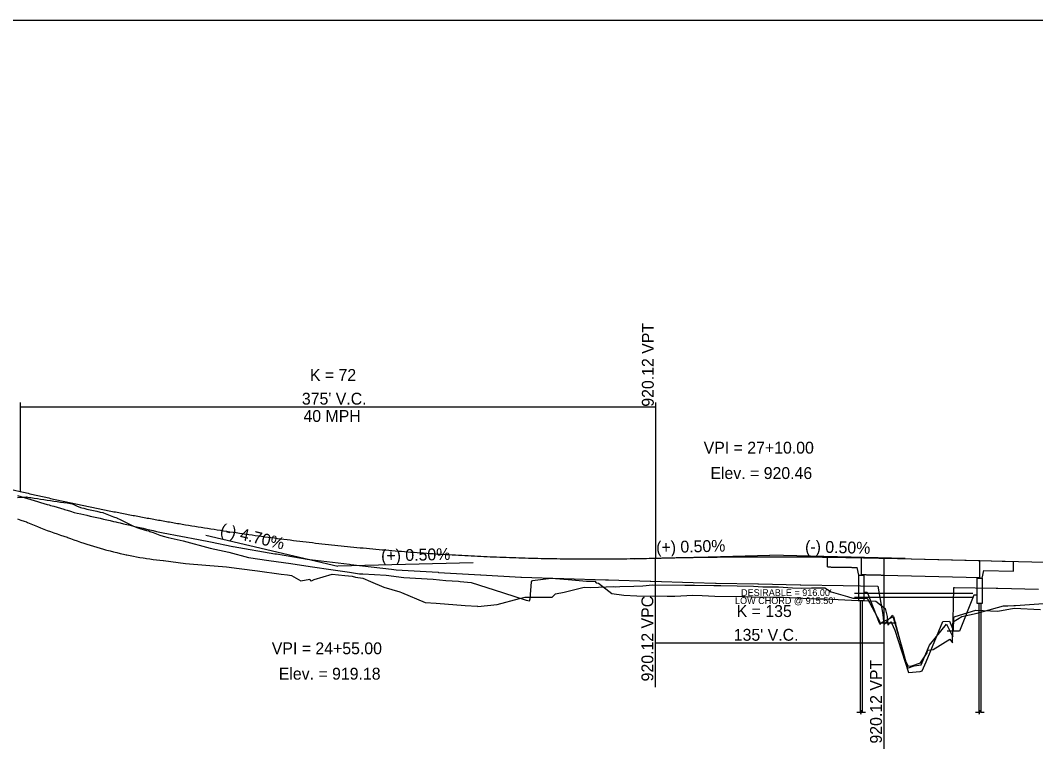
# Model space of a CAD drawing. Extents: x 1538426 to 1542651, y 1162537 to 1163637.
# Drawn here: x 1539693 to 1540293, y 1163207 to 1163637 of the extents above; entities that cross this region are included whole.
import ezdxf

# ---------------------------------------------------------------- set-up
doc = ezdxf.new("R2010")
doc.units = 0
for name, color, linetype in [('BR_CONCRETE', 7, 'Continuous'), ('BR_EXIST_GROUND_LT', 7, 'Continuous'), ('BR_EXIST_GROUND_RT', 7, 'Continuous'), ('BR_GROUND LINES', 7, 'Continuous'), ('BR_USER NOTES', 7, 'Continuous'), ('RD_DDB_GradeTX', 7, 'Continuous'), ('RD_DDB_Profile_EX', 7, 'Continuous'), ('RD_DDB_Profile_Lbl', 7, 'Continuous'), ('RD_DDB_Profile_PR', 7, 'Continuous'), ('RD_DDB_StripGrade', 7, 'Continuous'), ('RD_DDB_VCLbl', 7, 'Continuous'), ('RD_SHT_ShtClip', 7, 'Continuous')]:
    doc.layers.add(name, color=color, linetype=linetype)

msp = doc.modelspace()

# ---------------------------------------------------------------- linework, layer by layer
at = {"layer": 'BR_CONCRETE'}
for p, q in [((1540169.92, 1163314.12), (1540169.92, 1163319.95)), ((1540189.92, 1163319.63), (1540189.92, 1163309.63)), ((1540203.42, 1163319.33), (1540259.92, 1163317.92)), ((1540188.42, 1163309.21), (1540187.5, 1163313.84)), ((1540259.92, 1163307.92), (1540259.92, 1163317.92)), ((1540259.92, 1163317.92), (1540279.92, 1163317.42)), ((1540279.92, 1163311.59), (1540279.92, 1163317.42)), ((1540189.92, 1163309.63), (1540189.92, 1163309.21)), ((1540203.41, 1163309.33), (1540259.92, 1163307.92)), ((1540259.92, 1163307.92), (1540259.92, 1163307.5)), ((1540261.42, 1163307.5), (1540262.33, 1163312.03)), ((1540262.33, 1163312.03), (1540279.92, 1163311.59)), ((1540189.34, 1163294.21), (1540189.34, 1163228.4)), ((1540190.51, 1163294.21), (1540190.51, 1163228.4)), ((1540259.34, 1163292.5), (1540259.34, 1163228.4)), ((1540260.51, 1163292.5), (1540260.51, 1163228.4))]:
    msp.add_line(p, q, dxfattribs=at)
for points in [[(1540188.42, 1163309.21), (1540191.42, 1163309.21), (1540191.42, 1163294.21), (1540188.42, 1163294.21)], [(1540258.42, 1163307.5), (1540261.42, 1163307.5), (1540261.42, 1163292.5), (1540258.42, 1163292.5)]]:
    msp.add_lwpolyline(points, close=True, dxfattribs=at)
for points in [[(1540187.32, 1163228.4), (1540189.56, 1163228.4), (1540189.65, 1163227.23), (1540190.16, 1163229.64), (1540190.34, 1163228.4), (1540192.45, 1163228.4)], [(1540257.32, 1163228.4), (1540259.56, 1163228.4), (1540259.65, 1163227.23), (1540260.16, 1163229.64), (1540260.34, 1163228.4), (1540262.45, 1163228.4)]]:
    msp.add_lwpolyline(points, dxfattribs=at)
for points in [[(1540169.92, 1163319.95), (1540176.59, 1163319.87), (1540183.26, 1163319.76), (1540189.92, 1163319.63)], [(1540189.92, 1163319.63), (1540194.42, 1163319.54), (1540198.92, 1163319.44), (1540203.42, 1163319.33)], [(1540169.92, 1163314.12), (1540175.78, 1163314.05), (1540181.64, 1163313.95), (1540187.5, 1163313.84)], [(1540189.92, 1163309.63), (1540194.42, 1163309.54), (1540198.92, 1163309.44), (1540203.41, 1163309.33)]]:
    msp.add_open_spline(points, degree=2, dxfattribs=at)
at = {"layer": 'BR_EXIST_GROUND_LT'}
msp.add_lwpolyline([(1539691.76, 1163342.52), (1539693.72, 1163341.83), (1539695.67, 1163341.16), (1539697, 1163340.71), (1539697.63, 1163340.44), (1539699.58, 1163339.61), (1539701.53, 1163338.8), (1539703.49, 1163338), (1539705.44, 1163337.22), (1539707.4, 1163336.46), (1539709.35, 1163335.72), (1539711.31, 1163334.99), (1539712.2, 1163334.67), (1539713.26, 1163334.28), (1539715.21, 1163333.59), (1539717.17, 1163332.92), (1539719.12, 1163332.26), (1539721.08, 1163331.62), (1539721.38, 1163331.53), (1539723.03, 1163330.91), (1539724.98, 1163330.2), (1539726.94, 1163329.5), (1539728.89, 1163328.83), (1539730.85, 1163328.17), (1539731.59, 1163327.92), (1539732.8, 1163327.53), (1539734.76, 1163326.91), (1539736.71, 1163326.31), (1539738.66, 1163325.73), (1539740.62, 1163325.17), (1539742.57, 1163324.62), (1539743.72, 1163324.31), (1539744.53, 1163324.09), (1539746.48, 1163323.58), (1539748.43, 1163323.08), (1539750.39, 1163322.61), (1539752.34, 1163322.15), (1539754.3, 1163321.71), (1539755.85, 1163321.37), (1539756.25, 1163321.29), (1539758.21, 1163320.89), (1539760.16, 1163320.51), (1539762.11, 1163320.15), (1539764.07, 1163319.8), (1539766.02, 1163319.48), (1539767.2, 1163319.29), (1539767.98, 1163319.17), (1539769.93, 1163318.87), (1539771.88, 1163318.6), (1539773.84, 1163318.34), (1539775.79, 1163318.1), (1539777.75, 1163317.88), (1539778.05, 1163317.85), (1539791.04, 1163316.23), (1539803.05, 1163315.2), (1539815.1, 1163314.17), (1539822.57, 1163313.25), (1539833.4, 1163311.84), (1539847.53, 1163309.93), (1539851.16, 1163309.44), (1539853.56, 1163309.13), (1539859.05, 1163306.01), (1539864.41, 1163306.87), (1539864.6, 1163306.17), (1539865.38, 1163305.92), (1539867, 1163306.65), (1539877.6, 1163309.83), (1539884.94, 1163309.05), (1539889.36, 1163308.65), (1539891.28, 1163308.15), (1539895.66, 1163307.59), (1539900.16, 1163305.57), (1539908.15, 1163302.15), (1539917.52, 1163299.43), (1539918.52, 1163298.96), (1539932.53, 1163293.22), (1539938.94, 1163292.75), (1539956.06, 1163291.43), (1539963.28, 1163290.91), (1539963.62, 1163290.88), (1539974.97, 1163291.9), (1539988.11, 1163295.5), (1539991.25, 1163296.36), (1540007.49, 1163296.2), (1540009.46, 1163298.24), (1540014.57, 1163299.25), (1540026.4, 1163302.23), (1540030.3, 1163302.08), (1540043.79, 1163302.53), (1540045.04, 1163302.47), (1540047.34, 1163302.66), (1540055.58, 1163302.77), (1540061.06, 1163303.08), (1540066.72, 1163303.67), (1540085.71, 1163303.3), (1540091.4, 1163303.47), (1540102.86, 1163303.24), (1540107.11, 1163303.1), (1540126.41, 1163302.87), (1540131.8, 1163302.47), (1540135.2, 1163302.33), (1540141.03, 1163302.34), (1540149.41, 1163301.79), (1540154.44, 1163301.64), (1540160.51, 1163301.89), (1540168.35, 1163301.8), (1540172.12, 1163299.53), (1540181.86, 1163296.62), (1540184.97, 1163295.74), (1540193.52, 1163295.73), (1540200.73, 1163282.11), (1540200.94, 1163280.18), (1540202.22, 1163281.63), (1540209.05, 1163284.8), (1540215.91, 1163259.21), (1540217.48, 1163255.85), (1540219.15, 1163255.51), (1540224.95, 1163257.53), (1540228.87, 1163263.48), (1540229.1, 1163264.78), (1540229.54, 1163264.93), (1540232.39, 1163265.34), (1540242.17, 1163271.48), (1540243.74, 1163269.26), (1540243.97, 1163280.57), (1540244.12, 1163281.73), (1540249.37, 1163284.98), (1540258.46, 1163286.84), (1540273.95, 1163291.17), (1540276.4, 1163291.26), (1540279.95, 1163291.29), (1540280.94, 1163291.31), (1540297.45, 1163292.46)], dxfattribs=at)
at = {"layer": 'BR_EXIST_GROUND_RT'}
msp.add_lwpolyline([(1539691.76, 1163355.18), (1539693.72, 1163355.29), (1539695.67, 1163355.4), (1539697.16, 1163355.42), (1539697.63, 1163355.34), (1539698.91, 1163355.18), (1539699.58, 1163355.07), (1539701.53, 1163354.76), (1539703.49, 1163354.45), (1539705.44, 1163354.14), (1539707.4, 1163353.85), (1539709.35, 1163353.55), (1539711.31, 1163353.27), (1539713.26, 1163352.98), (1539715.21, 1163352.71), (1539717.17, 1163352.43), (1539719.12, 1163352.17), (1539721.08, 1163351.9), (1539723.03, 1163351.65), (1539723.66, 1163351.57), (1539724.98, 1163350.94), (1539726.94, 1163350.03), (1539728.48, 1163349.31), (1539728.89, 1163349.21), (1539729.83, 1163348.99), (1539730.85, 1163348.75), (1539732.8, 1163348.29), (1539734.76, 1163347.84), (1539736.71, 1163347.39), (1539738.66, 1163346.95), (1539740.62, 1163346.52), (1539742.1, 1163346.19), (1539742.57, 1163345.98), (1539744.53, 1163345.24), (1539746.48, 1163344.5), (1539748.43, 1163343.76), (1539750.39, 1163343.03), (1539750.7, 1163342.92), (1539752.34, 1163342.08), (1539754.3, 1163341.11), (1539756.25, 1163340.15), (1539758.21, 1163339.22), (1539760.16, 1163338.29), (1539762.26, 1163337.32), (1539764.07, 1163336.81), (1539766.02, 1163336.26), (1539767.98, 1163335.73), (1539769.34, 1163335.36), (1539769.93, 1163335.14), (1539771.88, 1163334.41), (1539773.84, 1163333.69), (1539775.79, 1163332.98), (1539777.75, 1163332.31), (1539780.67, 1163331.56), (1539789.63, 1163329.52), (1539805.59, 1163325.24), (1539816.46, 1163322.8), (1539828.12, 1163319.74), (1539840.22, 1163317.91), (1539853.12, 1163316.07), (1539864.6, 1163314.34), (1539878.11, 1163312.42), (1539887.83, 1163311.04), (1539893.65, 1163310.16), (1539895.65, 1163309.97), (1539909.43, 1163309.26), (1539919.9, 1163307.88), (1539937.15, 1163306.92), (1539944.57, 1163306.1), (1539952.17, 1163305.66), (1539953.17, 1163305.56), (1539959.65, 1163304.86), (1539978.18, 1163298.97), (1539978.66, 1163298.93), (1539992.06, 1163294.56), (1539994.15, 1163294.19), (1539994.39, 1163295.35), (1539995.26, 1163305.41), (1539995.77, 1163306.09), (1540006.78, 1163307.59), (1540016.83, 1163306.72), (1540027.73, 1163305.83), (1540032.32, 1163305.76), (1540032.64, 1163305.75), (1540033.49, 1163304.73), (1540034.72, 1163304.48), (1540042.72, 1163298.45), (1540049.85, 1163297.42), (1540057.5, 1163297.13), (1540075.39, 1163296.98), (1540079.96, 1163296.83), (1540090.6, 1163297.39), (1540096.03, 1163297.31), (1540103.44, 1163296.87), (1540121.14, 1163296.69), (1540125.63, 1163296.46), (1540138.16, 1163296.35), (1540144.05, 1163296.28), (1540163.17, 1163295.35), (1540168.48, 1163295.29), (1540188.19, 1163294.31), (1540190.29, 1163294.28), (1540198.55, 1163293.87), (1540203.36, 1163290.21), (1540204.13, 1163289.6), (1540205.2, 1163284.96), (1540205.66, 1163279.77), (1540207.48, 1163281.65), (1540207.84, 1163281.06), (1540209.79, 1163276.83), (1540217.79, 1163251.79), (1540224.64, 1163252.49), (1540225.87, 1163252.74), (1540228.23, 1163258.07), (1540238.16, 1163281.98), (1540242.05, 1163282.1), (1540244.43, 1163276.45), (1540244.53, 1163284.44), (1540245.32, 1163284.97), (1540257.53, 1163288.63), (1540270.61, 1163288.09), (1540280.3, 1163289.71), (1540295.74, 1163289.08)], dxfattribs=at)
at = {"layer": 'BR_GROUND LINES'}
for p, q in [((1540191.42, 1163299.21), (1540193.42, 1163299.21)), ((1540193.42, 1163299.21), (1540200.61, 1163281.24)), ((1540256.42, 1163297.5), (1540247.92, 1163276.24)), ((1540258.42, 1163297.5), (1540256.42, 1163297.5)), ((1540200.61, 1163281.24), (1540210.52, 1163281.24)), ((1540247.92, 1163276.24), (1540240.6, 1163276.24))]:
    msp.add_line(p, q, dxfattribs=at)
at = {"layer": 'BR_USER NOTES'}
for p, q in [((1540185.92, 1163298.72), (1540255.92, 1163298.72)), ((1540185.92, 1163296.22), (1540255.92, 1163296.22))]:
    msp.add_line(p, q, dxfattribs=at)
at = {"layer": 'RD_DDB_GradeTX'}
for p, q in [((1539803.05, 1163332.92), (1539880.92, 1163314.62)), ((1540055.95, 1163319.01), (1540135.92, 1163321.02)), ((1540215.9, 1163319.02), (1540135.92, 1163321.02)), ((1539960.9, 1163316.63), (1539880.92, 1163314.62))]:
    msp.add_line(p, q, dxfattribs=at)
at = {"layer": 'RD_DDB_Profile_EX'}
msp.add_lwpolyline([(1539691.76, 1163356.22), (1539693.72, 1163355.65), (1539695.67, 1163355.08), (1539697.63, 1163354.5), (1539699.58, 1163353.93), (1539701.53, 1163353.36), (1539703.49, 1163352.79), (1539705.44, 1163352.21), (1539707.4, 1163351.64), (1539709.35, 1163351.06), (1539710.46, 1163350.73), (1539710.88, 1163350.61), (1539711.31, 1163350.49), (1539713.26, 1163349.91), (1539715.21, 1163349.33), (1539717.17, 1163348.75), (1539719.12, 1163348.17), (1539719.47, 1163348.06), (1539721.08, 1163347.57), (1539723.03, 1163346.98), (1539725.28, 1163346.32), (1539726.94, 1163345.96), (1539729.09, 1163345.49), (1539730.85, 1163345.09), (1539732.8, 1163344.64), (1539734.76, 1163344.19), (1539736.71, 1163343.74), (1539738.66, 1163343.29), (1539740.62, 1163342.84), (1539742.57, 1163342.39), (1539744.53, 1163341.94), (1539746.48, 1163341.49), (1539748.43, 1163341.03), (1539749.75, 1163340.73), (1539750.39, 1163340.57), (1539751.42, 1163340.32), (1539752.34, 1163340.11), (1539754.3, 1163339.65), (1539756.25, 1163339.2), (1539758.21, 1163338.74), (1539760.16, 1163338.29), (1539762.11, 1163337.83), (1539764.07, 1163337.37), (1539766.02, 1163336.92), (1539767.98, 1163336.46), (1539769.93, 1163336), (1539771.88, 1163335.54), (1539773.84, 1163335.09), (1539775.79, 1163334.7), (1539777.75, 1163334.32), (1539798.69, 1163330.24), (1539805.69, 1163328.87), (1539818.81, 1163326.28), (1539819.19, 1163326.22), (1539843.73, 1163321.96), (1539844.67, 1163321.82), (1539862.71, 1163318.7), (1539864.4, 1163318.48), (1539887.71, 1163315.71), (1539888.56, 1163315.6), (1539912.65, 1163312.73), (1539915.36, 1163312.43), (1539940.06, 1163310.95), (1539940.36, 1163310.93), (1539965.05, 1163309.46), (1539965.37, 1163309.44), (1539988.95, 1163308.03), (1539989.28, 1163308.03), (1540013.94, 1163307.28), (1540014.3, 1163307.28), (1540038.97, 1163306.53), (1540040.42, 1163306.49), (1540040.79, 1163306.48), (1540065.41, 1163305.74), (1540065.79, 1163305.73), (1540090.61, 1163304.98), (1540103.91, 1163304.58), (1540104.27, 1163304.57), (1540128.91, 1163304.08), (1540129.26, 1163304.08), (1540153.91, 1163303.59), (1540154.25, 1163303.59), (1540179.18, 1163303.09), (1540199.66, 1163302.69), (1540202.63, 1163286.06), (1540203.3, 1163279.97), (1540204.85, 1163281.73), (1540208.48, 1163285.75), (1540213.98, 1163266.78), (1540217.24, 1163254.44), (1540221.26, 1163255.71), (1540225.41, 1163256.31), (1540230.24, 1163267.93), (1540240.32, 1163280.35), (1540244.08, 1163272.86), (1540244.57, 1163302.04), (1540245.03, 1163302.03), (1540269.57, 1163301.55), (1540270.52, 1163301.53), (1540294.57, 1163301.06)], dxfattribs=at)
at = {"layer": 'RD_DDB_Profile_PR'}
for p, q in [((1539625.92, 1163374.55), (1539693.42, 1163358.68)), ((1540203.42, 1163319.33), (1540318.42, 1163316.46))]:
    msp.add_line(p, q, dxfattribs=at)
for points in [[(1539693.42, 1163358.68), (1539700.92, 1163356.94), (1539708.42, 1163355.24), (1539715.92, 1163353.57), (1539723.42, 1163351.95), (1539730.92, 1163350.36), (1539738.42, 1163348.81), (1539745.92, 1163347.3), (1539753.42, 1163345.83), (1539760.92, 1163344.4), (1539768.42, 1163343.01), (1539775.92, 1163341.66), (1539783.42, 1163340.34), (1539790.92, 1163339.07), (1539798.42, 1163337.83), (1539805.92, 1163336.64), (1539813.42, 1163335.48), (1539820.92, 1163334.36), (1539828.42, 1163333.28), (1539835.92, 1163332.24), (1539843.42, 1163331.24), (1539850.92, 1163330.27), (1539858.42, 1163329.35), (1539865.92, 1163328.47), (1539873.42, 1163327.62), (1539880.92, 1163326.81), (1539888.42, 1163326.05), (1539895.92, 1163325.32), (1539903.42, 1163324.63), (1539910.92, 1163323.98), (1539918.42, 1163323.37), (1539925.92, 1163322.79), (1539933.42, 1163322.26), (1539940.92, 1163321.76), (1539948.42, 1163321.31), (1539955.92, 1163320.89), (1539963.42, 1163320.52), (1539970.92, 1163320.18), (1539978.42, 1163319.88), (1539985.92, 1163319.62), (1539993.42, 1163319.4), (1540000.92, 1163319.21), (1540008.42, 1163319.07), (1540015.92, 1163318.96), (1540023.42, 1163318.9), (1540030.92, 1163318.87), (1540038.42, 1163318.89), (1540045.92, 1163318.94), (1540053.42, 1163319.03), (1540060.92, 1163319.16), (1540068.42, 1163319.33)], [(1540068.42, 1163319.33), (1540071.12, 1163319.39), (1540073.82, 1163319.46), (1540076.52, 1163319.52), (1540079.22, 1163319.58), (1540081.92, 1163319.63), (1540084.62, 1163319.68), (1540087.32, 1163319.73), (1540090.02, 1163319.78), (1540092.72, 1163319.83), (1540095.42, 1163319.87), (1540098.12, 1163319.91), (1540100.82, 1163319.94), (1540103.52, 1163319.98), (1540106.22, 1163320.01), (1540108.92, 1163320.04), (1540111.62, 1163320.06), (1540114.32, 1163320.09), (1540117.02, 1163320.11), (1540119.72, 1163320.12), (1540122.42, 1163320.14), (1540125.12, 1163320.15), (1540127.82, 1163320.16), (1540130.52, 1163320.17), (1540133.22, 1163320.17), (1540135.92, 1163320.17), (1540138.62, 1163320.17), (1540141.32, 1163320.17), (1540144.02, 1163320.16), (1540146.72, 1163320.15), (1540149.42, 1163320.14), (1540152.12, 1163320.13), (1540154.82, 1163320.11), (1540157.52, 1163320.09), (1540160.22, 1163320.07), (1540162.92, 1163320.04), (1540165.62, 1163320.01), (1540168.32, 1163319.98), (1540171.02, 1163319.95), (1540173.72, 1163319.91), (1540176.42, 1163319.87), (1540179.12, 1163319.83), (1540181.82, 1163319.79), (1540184.52, 1163319.74), (1540187.22, 1163319.69), (1540189.92, 1163319.64), (1540192.62, 1163319.58), (1540195.32, 1163319.52), (1540198.02, 1163319.46), (1540200.72, 1163319.4), (1540203.42, 1163319.33)]]:
    msp.add_spline(points, degree=3, dxfattribs=at)
at = {"layer": 'RD_DDB_VCLbl'}
for p, q in [((1539693.42, 1163411.18), (1539693.42, 1163358.68)), ((1539693.42, 1163408.68), (1540068.42, 1163408.68)), ((1540068.42, 1163411.18), (1540068.42, 1163319.33)), ((1540068.42, 1163243.14), (1540068.42, 1163319.33)), ((1540203.42, 1163206.88), (1540203.42, 1163319.33)), ((1540068.42, 1163269.33), (1540203.42, 1163269.33))]:
    msp.add_line(p, q, dxfattribs=at)
at = {"layer": 'RD_SHT_ShtClip'}
msp.add_line((1539559.8, 1163636.73), (1541409.8, 1163636.73), dxfattribs=at)

# ---------------------------------------------------------------- texts
at = {"layer": 'BR_USER NOTES'}
for s, p in [("DESIRABLE = 916.00'", (1540118.97, 1163296.98)), ("LOW CHORD @ 915.50'", (1540115.42, 1163292.27))]:
    msp.add_text(s, height=4, dxfattribs=at).set_placement(p)
at = {"layer": 'RD_DDB_GradeTX'}
for s, rotation, p in [('(-) 4.70%', 346.77545, (1539810.98, 1163333.11)), ('(+) 0.50%', 1.43703, (1539906.54, 1163317.27)), ('(+) 0.50%', 1.43703, (1540068.95, 1163322.19)), ('(-) 0.50%', 358.5679, (1540156.71, 1163322.77))]:
    msp.add_text(s, height=7, rotation=rotation, dxfattribs=at).set_placement(p)
at = {"layer": 'RD_DDB_Profile_Lbl'}
for s, p in [('VPI = 27+10.00', (1540096.9, 1163381.02)), ('Elev. = 920.46', (1540100.87, 1163366.02)), ('VPI = 24+55.00', (1539841.9, 1163262.62)), ('Elev. = 919.18', (1539846.03, 1163247.62))]:
    msp.add_text(s, height=7, dxfattribs=at).set_placement(p)
at = {"layer": 'RD_DDB_StripGrade'}
for s, p in [('920.12 VPT', (1540067.42, 1163408.68)), ('920.12 VPC', (1540067.17, 1163246.59)), ('920.12 VPT', (1540202.14, 1163209.89))]:
    msp.add_text(s, height=7, rotation=90, dxfattribs=at).set_placement(p)
at = {"layer": 'RD_DDB_VCLbl'}
for s, p in [('K = 72', (1539864.39, 1163423.93)), ("375' V.C.", (1539859.67, 1163409.93)), ('40 MPH', (1539860.62, 1163399.72)), ('K = 135', (1540116.4, 1163284.58)), ("135' V.C.", (1540114.67, 1163270.58))]:
    msp.add_text(s, height=7, dxfattribs=at).set_placement(p)

doc.saveas('drawing.dxf')
